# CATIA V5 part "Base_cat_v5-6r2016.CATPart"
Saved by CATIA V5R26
Part number: Base
Bounding box of the stored display mesh (mm): x -24 to 24, y 0 to 90, z 0 to 54
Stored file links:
  D:\_Deepak\CATIA\CATIA V5 2015 Parts Files\Tutorial Files\Tutorials\c14_catia_v5_6r2016_tut\c14tut2\c14tut2.CATParts\Base_cat_v5-6r2016.CATPart
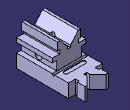
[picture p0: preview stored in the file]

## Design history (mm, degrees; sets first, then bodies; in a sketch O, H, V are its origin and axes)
Body1 (main body)
  Sketch1 on xy-plane, origin (0, 0, 0), H (1, 0, 0), V (0, 1, 0)
    line L1 (-24, 0) -> (24, 0)
    point P2 (24, 0)
    construction line L2 (-23.876, 50.8) -> (23.876, 50.8)
    point P3 (-23.876, 50.8)
    point P4 (23.876, 50.8)
    line L3 (24, 0) -> (24, 74)
    point P5 (24, 74)
    line L4 (24, 74) -> (14, 74)
    point P6 (14, 74)
    line L5 (14, 74) -> (14, 79)
    point P7 (14, 79)
    line L6 (14, 79) -> (16.5, 79)
    point P8 (16.5, 79)
    line L7 (16.5, 79) -> (16.5, 90)
    point P9 (16.5, 90)
    line L8 (16.5, 90) -> (13.5, 90)
    point P10 (13.5, 90)
    line L9 (13.5, 90) -> (2, 78.5)
    point P11 (2, 78.5)
    line L10 (2, 78.5) -> (2, 74)
    point P12 (2, 74)
    line L11 (2, 74) -> (0, 74)
    point P13 (0, 74)
    point P14 (0, 74)
    point P15 (-2, 74)
    line L12 (-2, 74) -> (0, 74)
    point P16 (-2, 78.5)
    line L13 (-2, 78.5) -> (-2, 74)
    point P17 (-13.5, 90)
    line L14 (-13.5, 90) -> (-2, 78.5)
    point P18 (-16.5, 90)
    line L15 (-16.5, 90) -> (-13.5, 90)
    point P19 (-16.5, 79)
    line L16 (-16.5, 79) -> (-16.5, 90)
    point P20 (-14, 79)
    line L17 (-14, 79) -> (-16.5, 79)
    point P21 (-14, 74)
    line L18 (-14, 74) -> (-14, 79)
    point P22 (-24, 74)
    line L19 (-24, 74) -> (-14, 74)
    point P23 (-23.876, 50.8)
    point P24 (23.876, 50.8)
    construction line L20 (23.876, 50.8) -> (-23.876, 50.8)
    point P25 (-24, 0)
    line L21 (-24, 0) -> (-24, 74)
    distance P2 V = 24
    distance L13 L10 = 4
    distance L16 L7 = 33
    distance L5 L3 = 10
    length L18 = 5
    angle L14 L9 = 90
    distance L4 L8 = 16
    distance P17 P10 = 27
    distance L1 L8 = 90
    length L1 = 48
    horizontal: L1 H, L2 H, L4 H, L6 H, L8 H, L11 H
    coincidence: H L1, P13 V, P13 P14, L12 L4
    vertical: L3 V, L5 V, L7 V, L10 V
    symmetry: P13 P14 V, P12 P15 V, L11 L12 V, P11 P16 V, L10 L13 V, P10 P17 V, L9 L14 V, P9 P18 V, L8 L15 V, P8 P19 V, L7 L16 V, P7 P20 V, L6 L17 V, P6 P21 V, L5 L18 V, P5 P22 V, L4 L19 V, P4 P23 V, P3 P24 V, L2 L20 V, P2 P25 V, L3 L21 V
  Pad1: profile Sketch1, direction (0, 0, 1), length 19
  Sketch2 on face of Pad1, origin (0, 0, 0), H (1, 0, 0), V (0, 0, 1)
    line L1 (17.5, 19) -> (17.5, 32)
    point P1 (17.5, 19)
    point P2 (17.5, 32)
    line L2 (17.5, 32) -> (24, 32)
    point P3 (24, 32)
    line L3 (24, 32) -> (24, 38)
    point P4 (24, 38)
    line L4 (24, 38) -> (13.5, 38)
    point P5 (13.5, 38)
    line L5 (13.5, 38) -> (13.5, 43)
    point P6 (13.5, 43)
    line L6 (13.5, 43) -> (16.5, 43)
    point P7 (16.5, 43)
    line L7 (16.5, 43) -> (16.5, 54)
    point P8 (16.5, 54)
    reference projected line E1 (24, 19) -> (-24, 19) from edge of Pad1
    reference projected line E2 (24, 0) -> (24, 19) from edge of Pad1
    line L8 (16.5, 54) -> (12.9083, 54)
    point P9 (12.9083, 54)
    point P10 (2, 41)
    line L9 (2, 41) -> (2, 38)
    point P11 (2, 38)
    line L10 (2, 38) -> (0, 38)
    point P12 (0, 38)
    line L11 (2, 41) -> (12.9083, 54)
    point P13 (-12.9083, 54)
    point P14 (-2, 41)
    line L12 (-2, 41) -> (-12.9083, 54)
    point P15 (0, 38)
    point P16 (-2, 38)
    line L13 (-2, 38) -> (0, 38)
    line L14 (-2, 41) -> (-2, 38)
    point P17 (-16.5, 54)
    line L15 (-16.5, 54) -> (-12.9083, 54)
    point P18 (-16.5, 43)
    line L16 (-16.5, 43) -> (-16.5, 54)
    point P19 (-13.5, 43)
    line L17 (-13.5, 43) -> (-16.5, 43)
    point P20 (-13.5, 38)
    line L18 (-13.5, 38) -> (-13.5, 43)
    point P21 (-24, 38)
    line L19 (-24, 38) -> (-13.5, 38)
    point P22 (-24, 32)
    line L20 (-24, 32) -> (-24, 38)
    point P23 (-17.5, 32)
    line L21 (-17.5, 32) -> (-24, 32)
    point P24 (-17.5, 19)
    line L22 (-17.5, 19) -> (-17.5, 32)
    line L23 (-17.5, 19) -> (17.5, 19)
    distance L2 H = 32
    distance L4 H = 38
    distance L6 H = 43
    distance L8 H = 54
    distance L9 V = 2
    length L9 = 3
    distance L22 L1 = 35
    distance L7 L16 = 33
    angle L12 L11 = 80
    distance L18 L5 = 27
    vertical: L1 V, L3 V, L5 V, L7 V, L9 V
    horizontal: L2 H, L4 H, L6 H, L8 H, L10 H, L23 H
    coincidence: P1 E1, L3 E2, P11 L4, P12 V, P12 P15
    symmetry: P9 P13 V, P10 P14 V, L11 L12 V, P12 P15 V, P11 P16 V, L10 L13 V, L9 L14 V, P8 P17 V, L8 L15 V, P7 P18 V, L7 L16 V, P6 P19 V, L6 L17 V, P5 P20 V, L5 L18 V, P4 P21 V, L4 L19 V, P3 P22 V, L3 L20 V, P2 P23 V, L2 L21 V, P1 P24 V, L1 L22 V
  Pad2: profile Sketch2, direction (0, 1, 0), length 50.8
  Sketch3 on face of Pad1, origin (4.0235, 27.8102, 0), H (1, 0, 0), V (0, -1, 0)
    point P1 (-4.0235, 2.8102)
    reference intersected line E1 through (-4.0235, 0) direction (0, 1) from yz-plane
    reference projected line E2 (-6.0235, 27.8102) -> (-16.9318, 27.8102) from edge [face of Pad2 from Sketch2.L12 | start face of Pad2]
    distance P1 E2 = 25
    coincidence: E1 P1
  Hole1: placed by Sketch3, at (0, 25, 0) direction (0, 0, 1), diameter 8, depth 54.102
  Sketch4 on face of Pad2, origin (17.5, 12.3932, 23.5222), H (0, 1, 0), V (0, 0, 1)
    point P1 (12.6068, 1.4778)
    reference projected line E1 (-12.3932, 8.4778) -> (-12.3932, -4.5222) from edge of Pad2
    reference projected line E2 (-12.3932, -23.5222) -> (61.6068, -23.5222) from edge of Pad1
    distance E1 P1 = 25
    distance E2 P1 = 25
  Hole2: placed by Sketch4, at (17.5, 25, 25) direction (-1, 0, 0), diameter 10, depth 54.102
  Sketch5 on face of Pad1, origin (0, 0, 19), H (1, 0, 0), V (0, 1, 0)
    construction line L1 (-24, 59) -> (24, 59)
    point P1 (-24, 59)
    point P2 (24, 59)
    construction line L2 (-12.5, 59) -> (12.5, 59)
    point P3 (-12.5, 59)
    point P4 (12.5, 59)
    line L3 (-12.5, 62) -> (12.5, 62)
    line L4 (12.5, 56) -> (-12.5, 56)
    arc A1 centre (12.5, 59) radius 3 from (12.5, 62) to (12.5, 56) cw
    arc A2 centre (-12.5, 59) radius 3 from (-12.5, 56) to (-12.5, 62) cw
    reference projected line E1 (24, 74) -> (24, 0) from edge of Pad1
    reference projected line E2 (-24, 74) -> (-24, 0) from edge of Pad1
    reference projected line E3 (24, 74) -> (14, 74) from edge [face of Pad1 from Sketch1.L4 | end face of Pad1]
    radius A1 = 3
    distance L2 E3 = 15
    length L2 = 25
    distance V P4 = 12.5
    horizontal: L1 H, L2 H
    coincidence: P3 L1, P2 E1, P1 E2
    tangency: A1 L3, A2 L3, A1 L4, A2 L4
    parallelism: L2 L3
  Pocket1: profile Sketch5, direction (0, 0, -1), length 1
  Sketch6 on face of Pad1, origin (24, 0, 0), H (0, 1, 0), V (0, 0, 1)
    point P1 (50.8, 19)
    line L1 (50.8, 19) -> (52.5321, 16)
    point P2 (52.5321, 16)
    line L2 (52.5321, 16) -> (54.2641, 19)
    line L3 (54.2641, 19) -> (50.8, 19)
    reference projected line E1 (74, 19) -> (0, 19) from edge of Pad1
    construction line L4 (52.5321, 16) -> (52.5321, 29.45)
    reference projected line E2 (50.8, 19) -> (50.8, 32) from edge [end face of Pad2 | face of Pad2 from Sketch2.L1]
    angle L1 L2 = 60
    distance P2 L3 = 3
    angle L4 L2 = 30
    horizontal: L3 H
    coincidence: L3 E1, P1 E2
    vertical: L4 V
  Pocket2: profile Sketch6, direction (-1, 0, 0), through (limit type 6)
